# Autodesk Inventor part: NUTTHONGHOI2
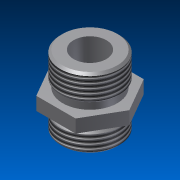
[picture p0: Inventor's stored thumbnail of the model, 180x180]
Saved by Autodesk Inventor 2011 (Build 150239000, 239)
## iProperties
Created: 2011-04
Part Number: NUTTHONGHOI2
Document SubType Name: Modeling
Designer: TRINH
Density: 1 g/cm^3
Author: TRINH
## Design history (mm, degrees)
sketch "Sketch1"
  geometry: C1 r 13.5 at (47.483, 48.152)
  constraints: 1 centre point
  dimensions: "d3" = 27 diameter of C1
extrude "Extrusion1" new body sketch "Sketch1" distance "d4" = 9; taper "d5" = 0 deg
sketch "Sketch2"
  geometry: C1 r 13.5 at (0, 0) reference; C2 r 12.5 at (0, 0); 1 further point
  constraints: 1 centre point, 1 coincident
  dimensions: "d6" = 25 diameter of C2
extrude "Extrusion2" join sketch "Sketch2" distance "d7" = 11; taper "d8" = 0 deg
sketch "Sketch4"
  geometry: C1 r 12.5 at (0, 0) reference; C2 r 13.5 at (0, 0); 1 further point
  constraints: 1 centre point, 1 coincident
  dimensions: "d10" = 27 diameter of C2
extrude "Extrusion3" join sketch "Sketch4" distance "d11" = 12; taper "d12" = 0 deg
workplane "Work Plane1"
sketch "Sketch5"
  geometry: L1 (18, 0)-(9, -15.588); L2 (9, -15.588)-(-9, -15.588); L3 (-9, -15.588)-(-18, 0); L4 (-18, 0)-(-9, 15.588); L5 (-9, 15.588)-(9, 15.588); L6 (9, 15.588)-(18, 0); C1 r 12.5 at (0, 0) reference; 2 further points
  constraints: 12 end point, 1 coincident, 13 other
  dimensions: "d14" = 36 distance of L3.end L1.start
extrude "Extrusion4" join sketch "Sketch5" distance "d15" = 6; taper "d16" = 0 deg
chamfer "Chamfer1" distance "d17" = 1; stored, may be unused: second distance "d18" = 2, angle "d19" = 45 deg
chamfer "Chamfer2" distance "d20" = 1; stored, may be unused: second distance "d21" = 2, angle "d22" = 45 deg
thread "Thread1" dims "d23" = 10, "d24" = 0
thread "Thread2" dims "d25" = 10, "d26" = 0
sketch "Sketch6"
  geometry: C1 r 12.5 at (0, 0) reference; C2 r 7.5 at (0, 0); 1 further point
  constraints: 1 centre point, 1 coincident
  dimensions: "d27" = 15 diameter of C2
extrude "Extrusion5" cut sketch "Sketch6" stored distance "d28" = 6; taper "d29" = 0 deg
body "Solid1"
other parameters: "d13" = -15
